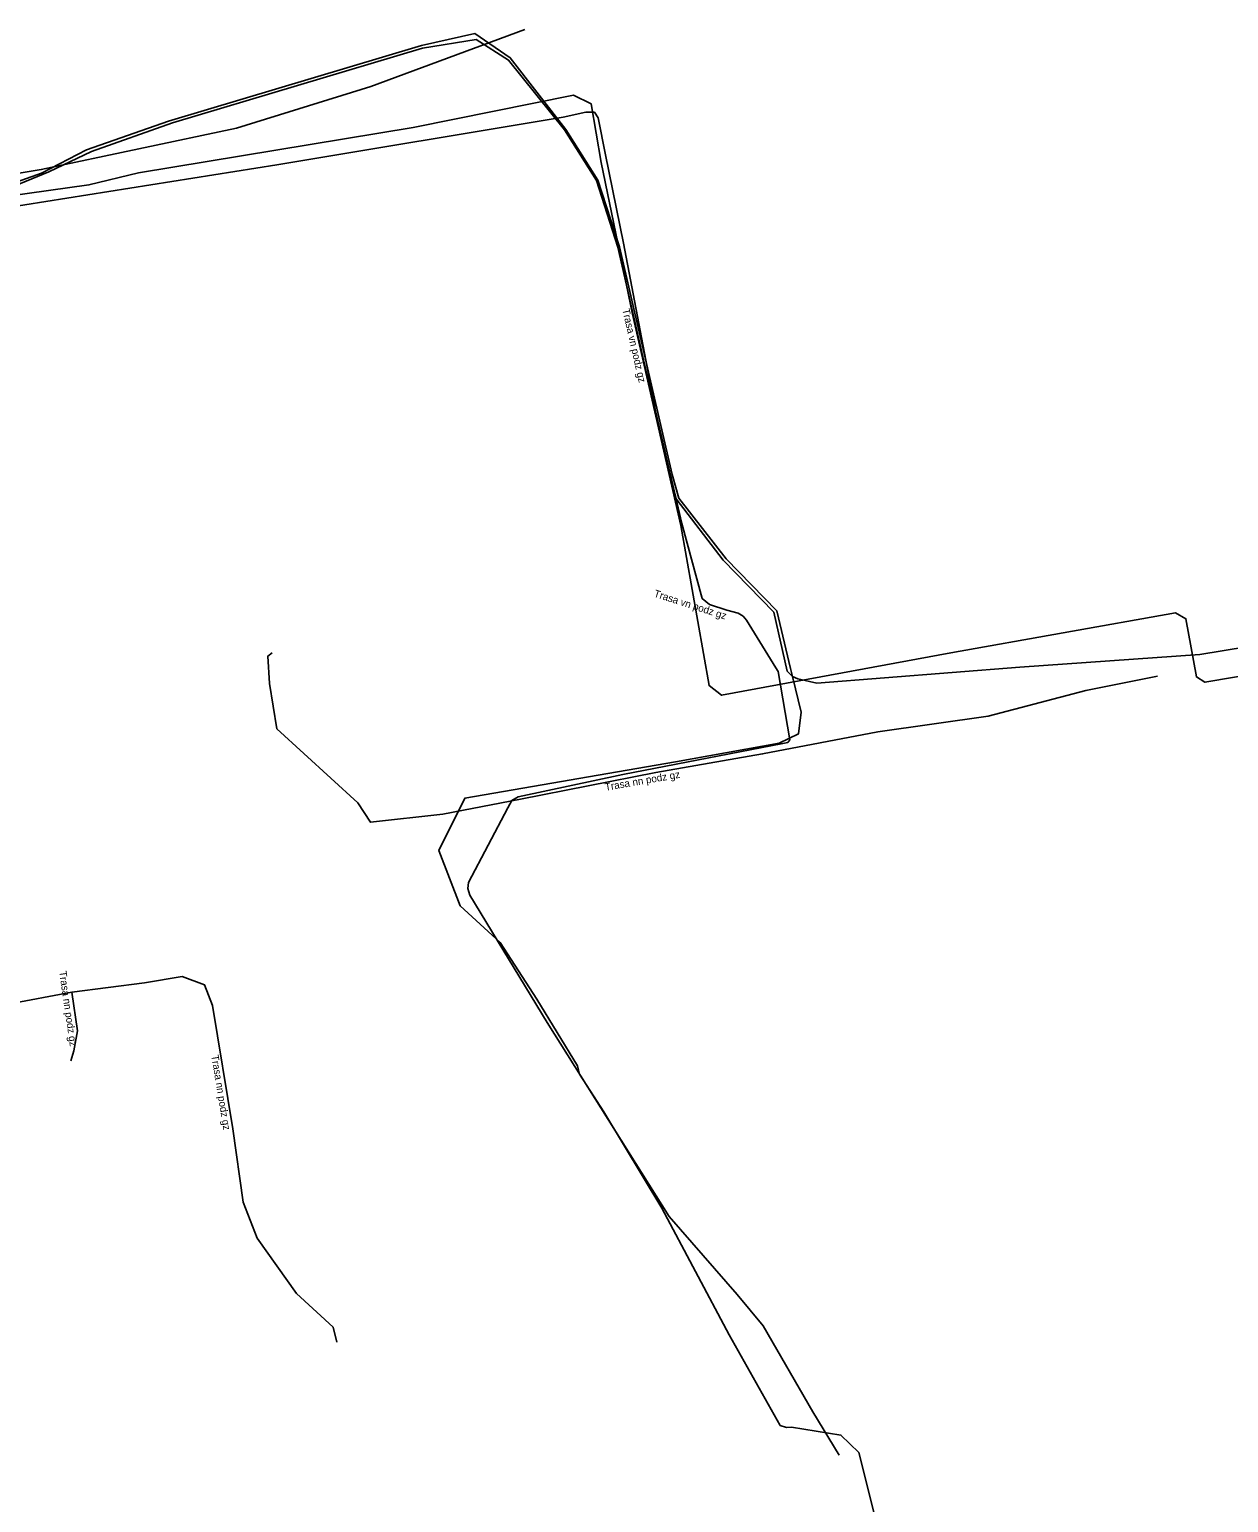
# Model space of a CAD drawing. Extents: x -473082 to -472599, y -1107914 to -1107370.
# Drawn here: x -472876.8 to -472795.3, y -1107725.3 to -1107625.2 of the extents above; entities that cross this region are included whole.
import ezdxf

# ---------------------------------------------------------------- set-up
doc = ezdxf.new("R2010")
doc.units = 0
for name, color, linetype in [('Popiskový text - Ostatní atributy Trasy', 7, 'Continuous'), ('Spojnice NN', 7, 'Continuous'), ('Spojnice VN', 7, 'Continuous')]:
    doc.layers.add(name, color=color, linetype=linetype)

msp = doc.modelspace()

# ---------------------------------------------------------------- linework, layer by layer
at = {"layer": 'Spojnice NN'}
for points in [[(-472843.13, -1107625.18), (-472853.58, -1107629.06), (-472862.7, -1107631.88), (-472875.97, -1107634.7), (-472883.29, -1107635.91)], [(-472800.15, -1107669.13), (-472805.01, -1107670.09), (-472811.66, -1107671.84), (-472819.14, -1107672.91), (-472826.98, -1107674.4), (-472834.22, -1107675.66), (-472843.42, -1107677.47), (-472848.7, -1107678.49), (-472853.61, -1107679.05), (-472854.46, -1107677.74), (-472859.98, -1107672.69), (-472860.46, -1107669.63), (-472860.58, -1107667.76), (-472860.28, -1107667.53)], [(-472855.89, -1107714.37), (-472856.15, -1107713.36), (-472858.64, -1107711.08), (-472861.31, -1107707.32), (-472862.26, -1107704.86), (-472862.95, -1107699.89), (-472864.33, -1107691.51), (-472864.88, -1107690.09), (-472866.4, -1107689.52), (-472868.96, -1107689.95), (-472873.9, -1107690.6)], [(-472873.9, -1107690.6), (-472878.21, -1107691.41), (-472879.98, -1107691.12), (-472883.62, -1107691.43), (-472884.35, -1107692.25), (-472884.48, -1107693.31)], [(-472873.9, -1107690.6), (-472873.52, -1107693.23), (-472873.76, -1107694.57), (-472873.96, -1107695.27)]]:
    msp.add_lwpolyline(points, dxfattribs=at)
at = {"layer": 'Spojnice VN'}
for points in [[(-472819.36, -1107726.2), (-472820.43, -1107721.88), (-472821.65, -1107720.69), (-472825.02, -1107720.14), (-472825.35, -1107720.18), (-472825.78, -1107720.03), (-472829.25, -1107713.88), (-472833.81, -1107705.28), (-472837.75, -1107698.72), (-472839.41, -1107696.17), (-472839.48, -1107695.9), (-472839.54, -1107695.61), (-472842.3, -1107691.08), (-472844.79, -1107687.23), (-472847.51, -1107684.72), (-472848.97, -1107680.97), (-472847.19, -1107677.41), (-472832.88, -1107674.94), (-472825.85, -1107673.67), (-472824.53, -1107673.04), (-472824.35, -1107671.56), (-472824.95, -1107669.15), (-472825.07, -1107668.61), (-472826.01, -1107664.68), (-472829.45, -1107661.14), (-472832.67, -1107657.02), (-472833.12, -1107655.41), (-472836.69, -1107639.94), (-472838.16, -1107635.41), (-472840.35, -1107631.97), (-472844.11, -1107627.1), (-472846.51, -1107625.46), (-472850.14, -1107626.26), (-472867.34, -1107631.41), (-472872.9, -1107633.36), (-472875.95, -1107634.94), (-472882.42, -1107637.24)], [(-472882.14, -1107637.59), (-472875.46, -1107634.86), (-472872.56, -1107633.48), (-472867.06, -1107631.52), (-472850.08, -1107626.46), (-472846.43, -1107625.87), (-472844.23, -1107627.26), (-472840.44, -1107632), (-472838.25, -1107635.45), (-472836.81, -1107639.97), (-472833.3, -1107655.38), (-472832.84, -1107657.08), (-472829.65, -1107661.24), (-472826.2, -1107664.78), (-472825.3, -1107668.78), (-472824.95, -1107669.15), (-472824.58, -1107669.3), (-472823.3, -1107669.59), (-472809.49, -1107668.52), (-472797.28, -1107667.66), (-472784.72, -1107665.6)], [(-472782.56, -1107667.11), (-472796.93, -1107669.53), (-472797.5, -1107669.17), (-472798.22, -1107665.22), (-472798.92, -1107664.82), (-472814.18, -1107667.54), (-472829.76, -1107670.42), (-472830.61, -1107669.76), (-472832.53, -1107658.88), (-472835.8, -1107644.53), (-472837.93, -1107634.22), (-472838.63, -1107630.23), (-472839.83, -1107629.65), (-472850.7, -1107631.84), (-472869.36, -1107634.92), (-472872.74, -1107635.74), (-472879.7, -1107636.72)], [(-472879.96, -1107637.54), (-472859.98, -1107634.38), (-472840.51, -1107631.13), (-472838.97, -1107630.81), (-472838.4, -1107630.81), (-472838.14, -1107631.19), (-472837.64, -1107633.7), (-472836.43, -1107639.71), (-472834.25, -1107651.1), (-472832.45, -1107658.75), (-472831.07, -1107663.84), (-472830.58, -1107664.26), (-472829.4, -1107664.64), (-472828.63, -1107664.85), (-472828.29, -1107665.05), (-472828.06, -1107665.32), (-472826.08, -1107668.55), (-472825.92, -1107668.81), (-472825.12, -1107673.44), (-472825.27, -1107673.64), (-472825.59, -1107673.7), (-472836.46, -1107675.8), (-472843.57, -1107677.33), (-472844, -1107677.56), (-472844.27, -1107678.06), (-472846.95, -1107683.14), (-472846.99, -1107683.54), (-472846.85, -1107684), (-472841.61, -1107692.66), (-472833.31, -1107705.83), (-472828.69, -1107711.14), (-472826.93, -1107713.26), (-472823.56, -1107719.12), (-472821.78, -1107722.05)]]:
    msp.add_lwpolyline(points, dxfattribs=at)

# ---------------------------------------------------------------- texts
at = {"layer": 'Popiskový text - Ostatní atributy Trasy'}
for s, rotation, p in [('Trasa vn podz gz', 282.8316, (-472836.51, -1107644.21)), ('Trasa vn podz gz', 342.1497, (-472834.4, -1107663.71)), ('Trasa nn podz gz', 9.8725, (-472837.64, -1107676.91)), ('Trasa nn podz gz', 278.2216, (-472874.76, -1107689.19)), ('Trasa nn podz gz', 279.3514, (-472864.43, -1107694.9))]:
    msp.add_text(s, height=0.5, rotation=rotation, dxfattribs=at).set_placement(p)

doc.saveas('drawing.dxf')
